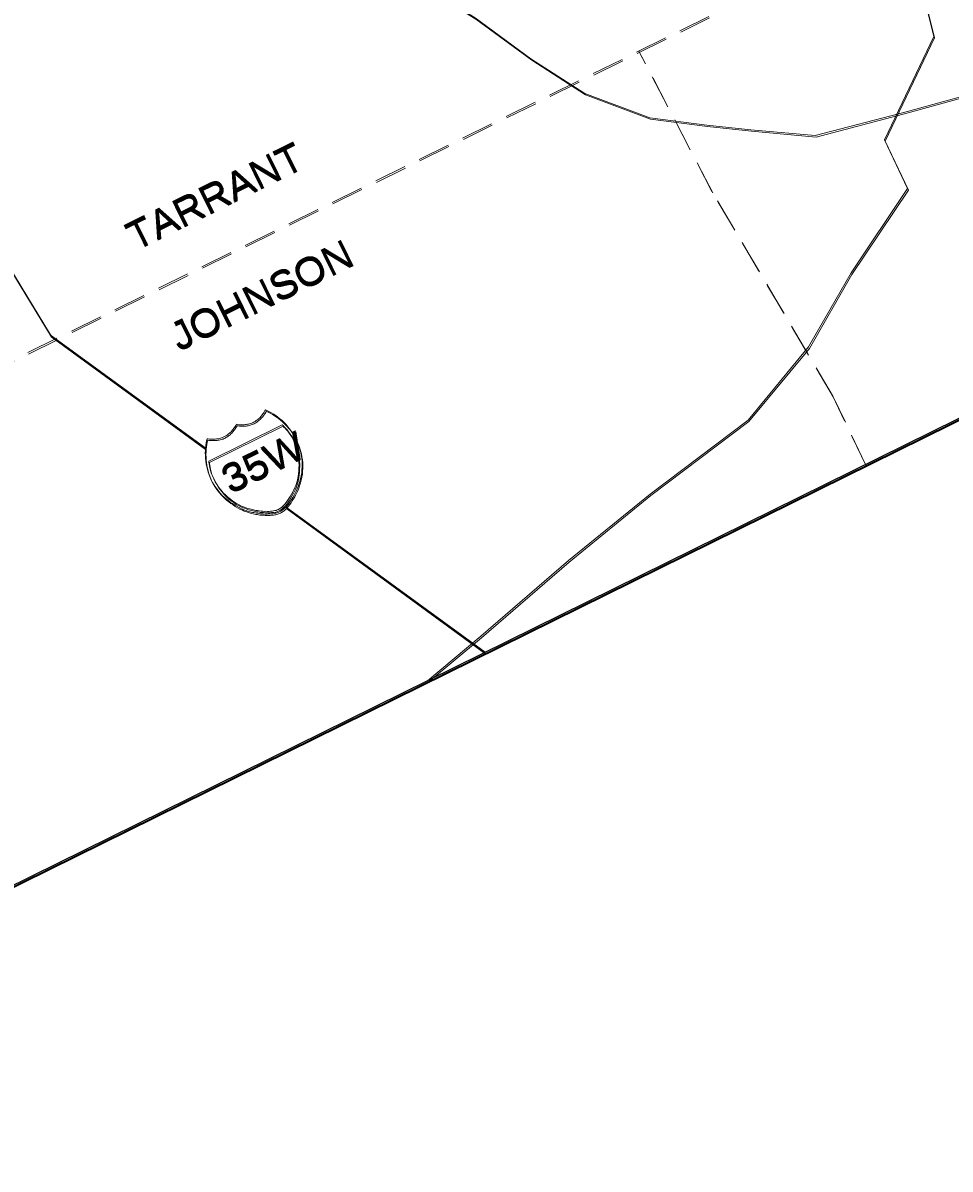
# Model space of a CAD drawing. Extents: x 2356606 to 2371222, y 6973096 to 6982644.
# Drawn here: x 2357350.8 to 2357523, y 6973406.8 to 6973619.6 of the extents above; entities that cross this region are included whole.
import ezdxf

# ---------------------------------------------------------------- set-up
doc = ezdxf.new("R2010")
doc.units = 0
doc.header["$LTSCALE"] = 2
doc.linetypes.add('MEDIUM_DASHED', pattern=[4.5, 3, -1.5])
doc.layers.add('62', color=7, linetype='Continuous', lineweight=13)
doc.layers.add('63', color=7, linetype='Continuous', lineweight=13)

msp = doc.modelspace()

# ---------------------------------------------------------------- linework, layer by layer
at = {"layer": '62', "linetype": 'MEDIUM_DASHED'}
msp.add_line((2357166.266, 6973466.488), (2357569.432, 6973665.465), dxfattribs=at)
at = {"layer": '62', "lineweight": 25}
msp.add_line((2357399.833, 6973529.439), (2357436.755, 6973502.471), dxfattribs=at)
for points in [[(2356999.05, 6973805.301), (2357204.965, 6973388.075), (2357608.13, 6973587.05), (2357402.214, 6974004.278)], [(2357271.1, 6973715.534), (2357293.579, 6973672.174), (2357318.873, 6973622.455), (2357356.041, 6973561.379), (2357384.703, 6973540.469)]]:
    msp.add_lwpolyline(points, dxfattribs=at)
at = {"layer": '62'}
for points in [[(2357515.838, 6973680.091), (2357514.8, 6973669.641), (2357513.692, 6973650.524), (2357516.541, 6973631.028), (2357520.059, 6973616.782), (2357510.893, 6973597.629), (2357515.222, 6973588.545), (2357504.737, 6973572.883), (2357496.836, 6973559.148), (2357485.626, 6973545.56), (2357467.399, 6973531.845), (2357452.222, 6973519.486), (2357435.966, 6973505.443), (2357426.061, 6973497.192)], [(2357533.197, 6973606.326), (2357524.62, 6973605.458), (2357515.167, 6973602.848), (2357498.075, 6973598.379), (2357486.108, 6973599.448), (2357477.959, 6973600.342), (2357467.348, 6973601.705), (2357455.307, 6973606.229), (2357445.287, 6973612.652), (2357434.9, 6973620.272), (2357421.318, 6973628.676), (2357410.865, 6973633.077), (2357401.996, 6973638.183), (2357391.636, 6973644.988), (2357385.904, 6973647.606), (2357373.931, 6973655.899)], [(2357391.466, 6973544.71), (2357391.67, 6973544.708), (2357391.891, 6973544.717), (2357392.062, 6973544.728), (2357392.283, 6973544.736), (2357392.485, 6973544.784), (2357392.675, 6973544.805), (2357392.857, 6973544.844), (2357393.048, 6973544.913), (2357393.229, 6973544.953), (2357393.432, 6973545.002), (2357393.593, 6973545.082), (2357393.776, 6973545.172), (2357393.936, 6973545.25), (2357394.096, 6973545.33), (2357394.278, 6973545.471), (2357394.401, 6973545.58), (2357394.551, 6973545.681), (2357394.714, 6973545.809), (2357394.865, 6973545.962), (2357395.007, 6973546.081), (2357395.149, 6973546.25), (2357395.281, 6973546.39), (2357395.402, 6973546.55), (2357395.524, 6973546.711), (2357395.646, 6973546.871), (2357395.776, 6973547.063), (2357395.897, 6973547.274), (2357396.001, 6973547.475), (2357396.38, 6973547.312), (2357396.754, 6973547.119), (2357397.134, 6973546.905), (2357397.534, 6973546.651), (2357397.908, 6973546.408), (2357398.298, 6973546.125), (2357398.68, 6973545.81), (2357399.071, 6973545.476), (2357399.45, 6973545.113), (2357399.812, 6973544.738), (2357400.159, 6973544.332), (2357400.48, 6973543.94), (2357400.79, 6973543.515), (2357401.1, 6973543.09), (2357401.351, 6973542.637), (2357401.621, 6973542.192), (2357401.829, 6973541.668), (2357402.057, 6973541.152), (2357402.227, 6973540.609), (2357402.393, 6973540.113), (2357402.553, 6973539.59), (2357402.631, 6973539.026), (2357402.719, 6973538.491), (2357402.776, 6973537.969), (2357402.793, 6973537.423), (2357402.79, 6973536.872), (2357402.748, 6973536.348), (2357402.713, 6973535.804), (2357402.611, 6973535.252), (2357402.495, 6973534.719), (2357402.364, 6973534.175), (2357402.178, 6973533.634), (2357402.056, 6973533.223), (2357401.904, 6973532.822), (2357401.709, 6973532.399), (2357401.525, 6973532.007), (2357401.292, 6973531.616), (2357401.057, 6973531.224), (2357400.834, 6973530.862), (2357400.613, 6973530.503), (2357400.379, 6973530.162), (2357400.127, 6973529.86), (2357399.873, 6973529.56), (2357399.612, 6973529.28), (2357399.367, 6973529.059), (2357399.115, 6973528.86), (2357398.851, 6973528.68), (2357398.62, 6973528.539)], [(2357398.62, 6973528.539), (2357398.448, 6973528.481), (2357398.308, 6973528.412), (2357398.137, 6973528.351), (2357397.977, 6973528.323), (2357397.793, 6973528.284), (2357397.613, 6973528.243), (2357397.38, 6973528.205), (2357397.168, 6973528.174), (2357396.968, 6973528.176), (2357396.756, 6973528.148), (2357396.503, 6973528.147), (2357396.282, 6973528.138), (2357396.04, 6973528.121), (2357395.832, 6973528.141), (2357395.567, 6973528.163), (2357395.316, 6973528.165), (2357395.076, 6973528.196), (2357394.813, 6973528.218), (2357394.564, 6973528.27), (2357394.322, 6973528.299), (2357394.079, 6973528.332), (2357393.82, 6973528.405), (2357393.577, 6973528.436), (2357393.346, 6973528.498), (2357393.085, 6973528.57), (2357392.854, 6973528.631), (2357392.623, 6973528.691), (2357392.402, 6973528.783), (2357392.141, 6973528.855), (2357391.93, 6973528.925), (2357391.728, 6973529.028), (2357391.508, 6973529.121), (2357391.107, 6973529.324), (2357390.653, 6973529.579), (2357390.254, 6973529.831), (2357389.854, 6973530.086), (2357389.443, 6973530.359), (2357389.051, 6973530.642), (2357388.681, 6973530.935), (2357388.339, 6973531.27), (2357387.979, 6973531.594), (2357387.628, 6973531.948), (2357387.328, 6973532.353), (2357387.019, 6973532.726), (2357386.697, 6973533.12), (2357386.448, 6973533.525), (2357386.17, 6973533.99), (2357385.918, 6973534.442), (2357385.731, 6973534.93), (2357385.541, 6973535.413), (2357385.373, 6973535.906), (2357385.223, 6973536.41), (2357385.106, 6973536.904), (2357384.999, 6973537.428), (2357384.921, 6973537.94), (2357384.843, 6973538.455), (2357384.836, 6973538.979), (2357384.816, 6973539.471), (2357384.83, 6973539.953), (2357384.861, 6973540.397), (2357384.925, 6973540.882), (2357384.949, 6973541.291), (2357385.041, 6973541.713), (2357385.144, 6973542.116), (2357385.364, 6973542.075), (2357385.606, 6973542.043), (2357385.839, 6973542.031), (2357386.04, 6973542.03), (2357386.261, 6973542.039), (2357386.462, 6973542.039), (2357386.673, 6973542.067), (2357386.876, 6973542.068), (2357387.055, 6973542.107), (2357387.246, 6973542.126), (2357387.447, 6973542.175), (2357387.62, 6973542.233), (2357387.843, 6973542.295), (2357388.004, 6973542.322), (2357388.165, 6973542.402), (2357388.366, 6973542.502), (2357388.527, 6973542.581), (2357388.688, 6973542.661), (2357388.85, 6973542.79), (2357388.992, 6973542.91), (2357389.142, 6973543.011), (2357389.284, 6973543.131), (2357389.456, 6973543.292), (2357389.601, 6973543.411), (2357389.722, 6973543.573), (2357389.853, 6973543.713), (2357389.994, 6973543.883), (2357390.136, 6973544.053), (2357390.257, 6973544.214), (2357390.369, 6973544.393), (2357390.473, 6973544.595), (2357390.593, 6973544.804), (2357390.813, 6973544.765), (2357391.034, 6973544.722), (2357391.267, 6973544.712), (2357391.466, 6973544.71)]]:
    msp.add_lwpolyline(points, dxfattribs=at)
at = {"layer": '62', "linetype": 'MEDIUM_DASHED'}
msp.add_lwpolyline([(2357507.402, 6973537.336), (2357501.29, 6973550.128), (2357478.892, 6973588.031), (2357465.33, 6973614.087)], dxfattribs=at)
at = {"layer": '62'}
msp.add_lwpolyline([(2357399.117, 6973544.722), (2357385.455, 6973537.978), (2357385.475, 6973537.739), (2357385.522, 6973537.436), (2357385.58, 6973537.115), (2357385.68, 6973536.709), (2357385.779, 6973536.256), (2357385.926, 6973535.753), (2357386.124, 6973535.249), (2357386.402, 6973534.68), (2357386.674, 6973534.139), (2357387.003, 6973533.571), (2357387.352, 6973533.067), (2357387.742, 6973532.581), (2357388.152, 6973532.106), (2357388.563, 6973531.682), (2357389.003, 6973531.246), (2357389.484, 6973530.882), (2357389.955, 6973530.538), (2357390.447, 6973530.203), (2357391, 6973529.898), (2357391.539, 6973529.613), (2357392.122, 6973529.4), (2357392.726, 6973529.193), (2357393.309, 6973529.029), (2357393.932, 6973528.887), (2357394.223, 6973528.803), (2357394.535, 6973528.781), (2357394.847, 6973528.71), (2357395.178, 6973528.697), (2357395.473, 6973528.666), (2357395.792, 6973528.625), (2357396.083, 6973528.644), (2357396.395, 6973528.622), (2357396.688, 6973528.64), (2357396.949, 6973528.67), (2357397.244, 6973528.689), (2357397.484, 6973528.707), (2357397.755, 6973528.765), (2357397.977, 6973528.825), (2357398.189, 6973528.905), (2357398.402, 6973528.986), (2357398.675, 6973529.145), (2357398.987, 6973529.373), (2357399.25, 6973529.653), (2357399.553, 6973529.956), (2357399.825, 6973530.264), (2357400.099, 6973530.626), (2357400.344, 6973530.997), (2357400.598, 6973531.396), (2357400.841, 6973531.82), (2357401.055, 6973532.251), (2357401.258, 6973532.652), (2357401.442, 6973533.043), (2357401.626, 6973533.435), (2357401.758, 6973533.827), (2357401.87, 6973534.21), (2357401.922, 6973534.511), (2357402.035, 6973535.095), (2357402.098, 6973535.627), (2357402.162, 6973536.158), (2357402.195, 6973536.701), (2357402.227, 6973537.197), (2357402.212, 6973537.691), (2357402.184, 6973538.152), (2357402.126, 6973538.625), (2357402.077, 6973539.078), (2357402.01, 6973539.521), (2357401.902, 6973539.947), (2357401.763, 6973540.378), (2357401.632, 6973540.792), (2357401.485, 6973541.195), (2357401.314, 6973541.59), (2357401.136, 6973541.952), (2357400.856, 6973542.519), (2357400.578, 6973542.982), (2357400.267, 6973543.409), (2357400.008, 6973543.78), (2357399.728, 6973544.095), (2357399.486, 6973544.328), (2357399.276, 6973544.55)], close=True, dxfattribs=at)
at = {"layer": '63', "lineweight": 35}
msp.add_line((2357204.965, 6973388.075), (2357788.759, 6973676.197), dxfattribs=at)
at = {"layer": '63', "linetype": 'MEDIUM_DASHED'}
msp.add_line((2357166.136, 6973466.751), (2357569.302, 6973665.728), dxfattribs=at)
at = {"layer": '63', "lineweight": 25}
msp.add_line((2357399.703, 6973529.702), (2357436.625, 6973502.734), dxfattribs=at)
for points in [[(2356998.92, 6973805.564), (2357204.835, 6973388.338), (2357608, 6973587.313), (2357402.084, 6974004.541)], [(2357270.97, 6973715.797), (2357293.449, 6973672.437), (2357318.743, 6973622.718), (2357355.911, 6973561.642), (2357384.573, 6973540.732)]]:
    msp.add_lwpolyline(points, dxfattribs=at)
at = {"layer": '63'}
for points in [[(2357515.708, 6973680.354), (2357514.67, 6973669.904), (2357513.562, 6973650.787), (2357516.411, 6973631.291), (2357519.929, 6973617.045), (2357510.763, 6973597.892), (2357515.092, 6973588.808), (2357504.607, 6973573.146), (2357496.706, 6973559.411), (2357485.496, 6973545.823), (2357467.269, 6973532.108), (2357452.092, 6973519.749), (2357435.836, 6973505.706), (2357425.931, 6973497.455)], [(2357533.067, 6973606.589), (2357524.49, 6973605.721), (2357515.037, 6973603.111), (2357497.945, 6973598.642), (2357485.978, 6973599.711), (2357477.829, 6973600.605), (2357467.218, 6973601.968), (2357455.177, 6973606.492), (2357445.157, 6973612.915), (2357434.77, 6973620.535), (2357421.188, 6973628.939), (2357410.735, 6973633.34), (2357401.866, 6973638.446), (2357391.506, 6973645.251), (2357385.774, 6973647.869), (2357373.801, 6973656.162)], [(2357391.336, 6973544.973), (2357391.54, 6973544.971), (2357391.761, 6973544.98), (2357391.932, 6973544.991), (2357392.153, 6973544.999), (2357392.355, 6973545.047), (2357392.545, 6973545.068), (2357392.727, 6973545.107), (2357392.918, 6973545.176), (2357393.099, 6973545.216), (2357393.302, 6973545.265), (2357393.463, 6973545.345), (2357393.646, 6973545.435), (2357393.806, 6973545.513), (2357393.966, 6973545.593), (2357394.148, 6973545.734), (2357394.271, 6973545.843), (2357394.421, 6973545.944), (2357394.584, 6973546.072), (2357394.735, 6973546.225), (2357394.877, 6973546.344), (2357395.019, 6973546.513), (2357395.151, 6973546.653), (2357395.272, 6973546.813), (2357395.394, 6973546.974), (2357395.516, 6973547.134), (2357395.646, 6973547.326), (2357395.767, 6973547.537), (2357395.871, 6973547.738), (2357396.25, 6973547.575), (2357396.624, 6973547.382), (2357397.004, 6973547.168), (2357397.404, 6973546.914), (2357397.778, 6973546.671), (2357398.168, 6973546.388), (2357398.55, 6973546.073), (2357398.941, 6973545.739), (2357399.32, 6973545.376), (2357399.682, 6973545.001), (2357400.029, 6973544.595), (2357400.35, 6973544.203), (2357400.66, 6973543.778), (2357400.97, 6973543.353), (2357401.221, 6973542.9), (2357401.491, 6973542.455), (2357401.699, 6973541.931), (2357401.927, 6973541.415), (2357402.097, 6973540.872), (2357402.263, 6973540.376), (2357402.423, 6973539.853), (2357402.501, 6973539.289), (2357402.589, 6973538.754), (2357402.646, 6973538.232), (2357402.663, 6973537.686), (2357402.66, 6973537.135), (2357402.618, 6973536.611), (2357402.583, 6973536.067), (2357402.481, 6973535.515), (2357402.365, 6973534.982), (2357402.234, 6973534.438), (2357402.048, 6973533.897), (2357401.926, 6973533.486), (2357401.774, 6973533.085), (2357401.579, 6973532.662), (2357401.395, 6973532.27), (2357401.162, 6973531.879), (2357400.927, 6973531.487), (2357400.704, 6973531.125), (2357400.483, 6973530.766), (2357400.249, 6973530.425), (2357399.997, 6973530.123), (2357399.743, 6973529.823), (2357399.482, 6973529.543), (2357399.237, 6973529.322), (2357398.985, 6973529.123), (2357398.721, 6973528.943), (2357398.49, 6973528.802)], [(2357398.49, 6973528.802), (2357398.318, 6973528.744), (2357398.178, 6973528.675), (2357398.007, 6973528.614), (2357397.847, 6973528.586), (2357397.663, 6973528.547), (2357397.483, 6973528.506), (2357397.25, 6973528.468), (2357397.038, 6973528.437), (2357396.838, 6973528.439), (2357396.626, 6973528.411), (2357396.373, 6973528.41), (2357396.152, 6973528.401), (2357395.91, 6973528.384), (2357395.702, 6973528.404), (2357395.437, 6973528.426), (2357395.186, 6973528.428), (2357394.946, 6973528.459), (2357394.683, 6973528.481), (2357394.434, 6973528.533), (2357394.192, 6973528.562), (2357393.949, 6973528.595), (2357393.69, 6973528.668), (2357393.447, 6973528.699), (2357393.216, 6973528.761), (2357392.955, 6973528.833), (2357392.724, 6973528.894), (2357392.493, 6973528.954), (2357392.272, 6973529.046), (2357392.011, 6973529.118), (2357391.8, 6973529.188), (2357391.598, 6973529.291), (2357391.378, 6973529.384), (2357390.977, 6973529.587), (2357390.523, 6973529.842), (2357390.124, 6973530.094), (2357389.724, 6973530.349), (2357389.313, 6973530.622), (2357388.921, 6973530.905), (2357388.551, 6973531.198), (2357388.209, 6973531.533), (2357387.849, 6973531.857), (2357387.498, 6973532.211), (2357387.198, 6973532.616), (2357386.889, 6973532.989), (2357386.567, 6973533.383), (2357386.318, 6973533.788), (2357386.04, 6973534.253), (2357385.788, 6973534.705), (2357385.601, 6973535.193), (2357385.411, 6973535.676), (2357385.243, 6973536.169), (2357385.093, 6973536.673), (2357384.976, 6973537.167), (2357384.869, 6973537.691), (2357384.791, 6973538.203), (2357384.713, 6973538.718), (2357384.706, 6973539.242), (2357384.686, 6973539.734), (2357384.7, 6973540.216), (2357384.731, 6973540.66), (2357384.795, 6973541.145), (2357384.819, 6973541.554), (2357384.911, 6973541.976), (2357385.014, 6973542.379), (2357385.234, 6973542.338), (2357385.476, 6973542.306), (2357385.709, 6973542.294), (2357385.91, 6973542.293), (2357386.131, 6973542.302), (2357386.332, 6973542.302), (2357386.543, 6973542.33), (2357386.746, 6973542.331), (2357386.925, 6973542.37), (2357387.116, 6973542.389), (2357387.317, 6973542.438), (2357387.49, 6973542.496), (2357387.713, 6973542.558), (2357387.874, 6973542.585), (2357388.035, 6973542.665), (2357388.236, 6973542.765), (2357388.397, 6973542.844), (2357388.558, 6973542.924), (2357388.72, 6973543.053), (2357388.862, 6973543.173), (2357389.012, 6973543.274), (2357389.154, 6973543.394), (2357389.326, 6973543.555), (2357389.471, 6973543.674), (2357389.592, 6973543.836), (2357389.723, 6973543.976), (2357389.864, 6973544.146), (2357390.006, 6973544.316), (2357390.127, 6973544.477), (2357390.239, 6973544.656), (2357390.343, 6973544.858), (2357390.463, 6973545.067), (2357390.683, 6973545.028), (2357390.904, 6973544.985), (2357391.137, 6973544.975), (2357391.336, 6973544.973)]]:
    msp.add_lwpolyline(points, dxfattribs=at)
at = {"layer": '63', "linetype": 'MEDIUM_DASHED'}
msp.add_lwpolyline([(2357507.272, 6973537.599), (2357501.16, 6973550.391), (2357478.762, 6973588.294), (2357465.2, 6973614.35)], dxfattribs=at)
at = {"layer": '63'}
msp.add_lwpolyline([(2357398.987, 6973544.985), (2357385.325, 6973538.241), (2357385.345, 6973538.002), (2357385.392, 6973537.699), (2357385.45, 6973537.378), (2357385.55, 6973536.972), (2357385.649, 6973536.519), (2357385.796, 6973536.016), (2357385.994, 6973535.512), (2357386.272, 6973534.943), (2357386.544, 6973534.402), (2357386.873, 6973533.834), (2357387.222, 6973533.33), (2357387.612, 6973532.844), (2357388.022, 6973532.369), (2357388.433, 6973531.945), (2357388.873, 6973531.509), (2357389.354, 6973531.145), (2357389.825, 6973530.801), (2357390.317, 6973530.466), (2357390.87, 6973530.161), (2357391.409, 6973529.876), (2357391.992, 6973529.663), (2357392.596, 6973529.456), (2357393.179, 6973529.292), (2357393.802, 6973529.15), (2357394.093, 6973529.066), (2357394.405, 6973529.044), (2357394.717, 6973528.973), (2357395.048, 6973528.96), (2357395.343, 6973528.929), (2357395.662, 6973528.888), (2357395.953, 6973528.907), (2357396.265, 6973528.885), (2357396.558, 6973528.903), (2357396.819, 6973528.933), (2357397.114, 6973528.952), (2357397.354, 6973528.97), (2357397.625, 6973529.028), (2357397.847, 6973529.088), (2357398.059, 6973529.168), (2357398.272, 6973529.249), (2357398.545, 6973529.408), (2357398.857, 6973529.636), (2357399.12, 6973529.916), (2357399.423, 6973530.219), (2357399.695, 6973530.527), (2357399.969, 6973530.889), (2357400.214, 6973531.26), (2357400.468, 6973531.659), (2357400.711, 6973532.083), (2357400.925, 6973532.514), (2357401.128, 6973532.915), (2357401.312, 6973533.306), (2357401.496, 6973533.698), (2357401.628, 6973534.09), (2357401.74, 6973534.473), (2357401.792, 6973534.774), (2357401.905, 6973535.358), (2357401.968, 6973535.89), (2357402.032, 6973536.421), (2357402.065, 6973536.964), (2357402.097, 6973537.46), (2357402.082, 6973537.954), (2357402.054, 6973538.415), (2357401.996, 6973538.888), (2357401.947, 6973539.341), (2357401.88, 6973539.784), (2357401.772, 6973540.21), (2357401.633, 6973540.641), (2357401.502, 6973541.055), (2357401.355, 6973541.458), (2357401.184, 6973541.853), (2357401.006, 6973542.215), (2357400.726, 6973542.782), (2357400.448, 6973543.245), (2357400.137, 6973543.672), (2357399.878, 6973544.043), (2357399.598, 6973544.358), (2357399.356, 6973544.591), (2357399.146, 6973544.813)], close=True, dxfattribs=at)

# ---------------------------------------------------------------- texts
at = {"layer": '62'}
for s, width, p in [('TARRANT', 1.1, (2357371.758, 6973577.115)), ('JOHNSON', 1.1, (2357379.895, 6973558.495)), ('35W', 1.15, (2357389.41, 6973531.998))]:
    msp.add_text(s, height=5.099, rotation=26.268, dxfattribs=dict(at, width=width)).set_placement(p)
at = {"layer": '63'}
for s, width, p in [('TARRANT', 1.1, (2357371.628, 6973577.379)), ('JOHNSON', 1.1, (2357379.765, 6973558.759)), ('35W', 1.15, (2357389.28, 6973532.262))]:
    msp.add_text(s, height=5.099, rotation=26.268, dxfattribs=dict(at, width=width)).set_placement(p)

doc.saveas('drawing.dxf')
